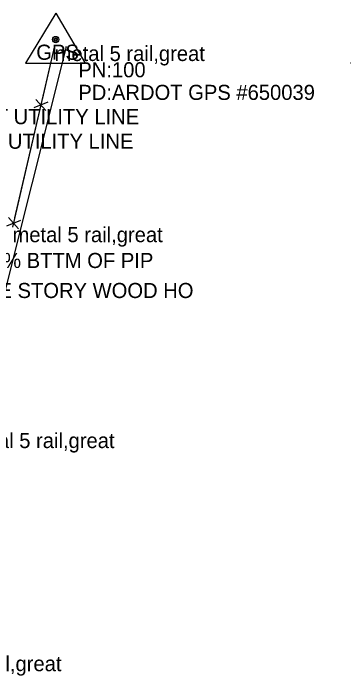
# Model space of a CAD drawing. Extents: x -99999 to 591807, y -99999 to 347168.
# Drawn here: x 591320.1 to 591432, y 322835.9 to 323055.3 of the extents above; entities that cross this region are included whole.
import ezdxf

# ---------------------------------------------------------------- set-up
doc = ezdxf.new("R2010")
doc.units = 0
for name, color, linetype in [('S_ELECTRIC_UTILITIES_ANNOT', 7, 'Continuous'), ('S_FENCE', 7, 'Continuous'), ('S_FENCE_ANNOT', 7, 'Continuous'), ('S_MSC_PT_SYM', 7, 'Continuous'), ('S_PRIMARY_CTL', 7, 'Continuous'), ('S_PRIMARY_CTL_ANNOT', 7, 'Continuous'), ('S_SIDE_DRAIN_ANNOT', 7, 'Continuous'), ('S_SURVEY_TEXT_ANNOT', 7, 'Continuous'), ('S_UTL_PT_SYM', 7, 'Continuous'), ('S_WATER_UTILITIES', 7, 'Continuous')]:
    doc.layers.add(name, color=color, linetype=linetype)

msp = doc.modelspace()

# ---------------------------------------------------------------- linework, layer by layer
at = {"layer": 'S_FENCE'}
for p, q in [((591333.85, 323044.48), (591319.88, 322984.49)), ((591327.63, 323026.77), (591330.97, 323023.05)), ((591331.62, 323025.84), (591326.98, 323023.98)), ((591318.51, 322987.63), (591321.85, 322983.91)), ((591322.5, 322986.7), (591317.86, 322984.84))]:
    msp.add_line(p, q, dxfattribs=at)
for points in [[(591333.85, 323044.48), (591329.71, 323026.69)], [(591328.88, 323023.13), (591320.6, 322987.55)]]:
    msp.add_lwpolyline(points, dxfattribs=at)
at = {"layer": 'S_MSC_PT_SYM'}
for points in [[(591333.85, 323044.48), (591333.85, 323044.53), (591333.85, 323044.48), (591333.8, 323044.48), (591333.85, 323044.48), (591333.85, 323044.43), (591333.85, 323044.48), (591333.9, 323044.48)], [(591431.94, 323038.88), (591431.94, 323038.93), (591431.94, 323038.88), (591431.89, 323038.88), (591431.94, 323038.88), (591431.94, 323038.83), (591431.94, 323038.88), (591431.99, 323038.88)]]:
    msp.add_lwpolyline(points, dxfattribs=at)
at = {"layer": 'S_PRIMARY_CTL'}
for p, q in [((591334.2, 323055.31), (591324.16, 323038.79)), ((591334.2, 323055.31), (591344.02, 323038.79)), ((591324.16, 323038.79), (591344.02, 323038.79))]:
    msp.add_line(p, q, dxfattribs=at)
for radius in [1.04, 0.609, 0.344]:
    msp.add_circle((591334.2, 323046.6), radius, dxfattribs=at)
at = {"layer": 'S_UTL_PT_SYM'}
msp.add_lwpolyline([(591337.62, 323044.16), (591337.62, 323044.21), (591337.62, 323044.16), (591337.57, 323044.16), (591337.62, 323044.16), (591337.62, 323044.11), (591337.62, 323044.16), (591337.67, 323044.16)], dxfattribs=at)
at = {"layer": 'S_WATER_UTILITIES'}
msp.add_line((591337.62, 323044.16), (591308.51, 322928.1), dxfattribs=at)

# ---------------------------------------------------------------- texts
at = {"layer": 'S_ELECTRIC_UTILITIES_ANNOT'}
for p in [(591290.16, 323018.56), (591288.26, 323010.42)]:
    msp.add_text('LOWEST UTILITY LINE', height=5, dxfattribs=at).set_placement(p)
at = {"layer": 'S_FENCE_ANNOT'}
for p in [(591333.85, 323039.48), (591319.88, 322979.49), (591303.91, 322911.29), (591286.33, 322837.41)]:
    msp.add_text('metal 5 rail,great', height=5, dxfattribs=at).set_placement(p)
at = {"layer": 'S_PRIMARY_CTL'}
msp.add_text('GPS', height=5, rotation=360, dxfattribs=at).set_placement((591327.76, 323039.9))
at = {"layer": 'S_PRIMARY_CTL_ANNOT'}
for s, p in [('PN:100', (591341.7, 323034.1)), ('PD:ARDOT GPS #650039', (591341.7, 323026.6))]:
    msp.add_text(s, height=5, dxfattribs=at).set_placement(p)
at = {"layer": 'S_SIDE_DRAIN_ANNOT'}
msp.add_text('DI:14" TY:RCP CN:5% BTTM OF PIP', height=5, dxfattribs=at).set_placement((591254.97, 322970.93))
at = {"layer": 'S_SURVEY_TEXT_ANNOT'}
msp.add_text('ASPHALT DW TO ONE STORY WOOD HO', height=5, dxfattribs=at).set_placement((591248.74, 322960.99))

doc.saveas('drawing.dxf')
